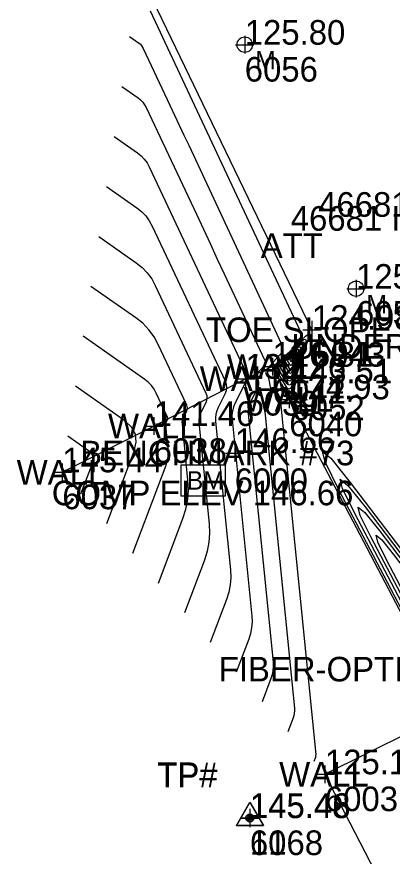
# Model space of a CAD drawing. Extents: x 13482745 to 13483091, y 311698 to 312158.
# Drawn here: x 13482867.1 to 13482915.9, y 311863.1 to 311972.3 of the extents above; entities that cross this region are included whole.
import ezdxf

# ---------------------------------------------------------------- set-up
doc = ezdxf.new("R2010")
doc.units = 0
for name, color, linetype in [('V-BLDG-OTLN', 7, 'Continuous'), ('V-PROP-IDEN', 7, 'Continuous'), ('V-PROP-MONM', 7, 'Continuous'), ('V-SITE-FEAT', 7, 'Continuous'), ('V-SITE-IDEN', 7, 'Continuous'), ('V-SITE-SPOT', 7, 'Continuous'), ('V-SURV-DATA', 7, 'Continuous'), ('V-SURV-IDEN', 7, 'Continuous'), ('V-SURV-PNTS', 7, 'Continuous'), ('V-SURV-SPOT', 7, 'Continuous'), ('V-TOPO-DRAN-SPOT', 7, 'Continuous'), ('V-TOPO-DRAN-TOE', 7, 'Continuous'), ('V-TOPO-LINE-IDEN', 7, 'Continuous'), ('V-TOPO-MAJR', 7, 'Continuous'), ('V-TOPO-MINR', 7, 'Continuous')]:
    doc.layers.add(name, color=color, linetype=linetype)

msp = doc.modelspace()

# ---------------------------------------------------------------- linework, layer by layer
at = {"layer": 'V-BLDG-OTLN'}
for points in [[(13482873.01, 311913.06), (13482884.9, 311919.08), (13482896.84, 311925.24), (13482900.36, 311926.81)], [(13482938.74, 311812.01), (13482914.39, 311859.78), (13482907.17, 311873.79), (13482923.79, 311882.04), (13482902.53, 311922.55), (13482900.37, 311926.81)]]:
    msp.add_lwpolyline(points, dxfattribs=at)
at = {"layer": 'V-SITE-FEAT'}
for centre in [(13482896.74, 311968.68), (13482911.22, 311936.94)]:
    msp.add_circle(centre, 1, dxfattribs=at)
at = {"layer": 'V-SITE-SPOT'}
for p, q in [((13482896.74, 311969.84), (13482896.74, 311967.52)), ((13482895.54, 311968.68), (13482897.94, 311968.68)), ((13482911.22, 311938.1), (13482911.22, 311935.78)), ((13482910.02, 311936.94), (13482912.42, 311936.94)), ((13482900.36, 311927.97), (13482900.36, 311925.65)), ((13482900.37, 311927.97), (13482900.37, 311925.65)), ((13482896.84, 311926.4), (13482896.84, 311924.08)), ((13482899.16, 311926.81), (13482901.56, 311926.81)), ((13482899.17, 311926.81), (13482901.57, 311926.81)), ((13482895.64, 311925.24), (13482898.04, 311925.24)), ((13482902.83, 311924.2), (13482902.83, 311921.88)), ((13482901.63, 311923.04), (13482904.03, 311923.04)), ((13482902.53, 311923.71), (13482902.53, 311921.39)), ((13482901.33, 311922.55), (13482903.73, 311922.55)), ((13482884.9, 311920.24), (13482884.9, 311917.92)), ((13482883.7, 311919.08), (13482886.1, 311919.08)), ((13482873.01, 311914.22), (13482873.01, 311911.9)), ((13482871.81, 311913.06), (13482874.21, 311913.06)), ((13482907.17, 311874.95), (13482907.17, 311872.63)), ((13482905.97, 311873.79), (13482908.37, 311873.79))]:
    msp.add_line(p, q, dxfattribs=at)
at = {"layer": 'V-SURV-DATA'}
for p, q in [((13482895.44, 311916.73), (13482895.44, 311914.41)), ((13482894.24, 311915.57), (13482896.64, 311915.57)), ((13482894.24, 311914.01), (13482888.41, 311914.01)), ((13482888.41, 311914.01), (13482888.41, 311910.01)), ((13482894.24, 311910.01), (13482894.24, 311914.01)), ((13482888.41, 311910.01), (13482894.24, 311910.01))]:
    msp.add_line(p, q, dxfattribs=at)
for points in [[(13482897.41, 311870.15), (13482899.17, 311867.11), (13482895.65, 311867.11)], [(13482897.41, 311870.15), (13482899.17, 311867.11), (13482895.65, 311867.11)], [(13482897.41, 311870.15), (13482899.17, 311867.11), (13482895.65, 311867.11)], [(13482897.41, 311870.1), (13482899.17, 311867.06), (13482895.65, 311867.06)]]:
    msp.add_lwpolyline(points, close=True, dxfattribs=at)
for centre, radius in [((13482897.41, 311868.13), 0.508), ((13482897.41, 311868.13), 0.508), ((13482897.41, 311868.13), 0.508), ((13482897.41, 311868.08), 0.508), ((13482897.41, 311868.08), 0.305), ((13482897.41, 311868.13), 0.305), ((13482897.41, 311868.13), 0.305), ((13482897.41, 311868.13), 0.305), ((13482897.41, 311868.13), 0.102), ((13482897.41, 311868.13), 0.102), ((13482897.41, 311868.13), 0.102), ((13482897.41, 311868.08), 0.102)]:
    msp.add_circle(centre, radius, dxfattribs=at)
at = {"layer": 'V-SURV-SPOT'}
for p, q in [((13482895.44, 311916.73), (13482895.44, 311914.41)), ((13482894.24, 311915.57), (13482896.64, 311915.57)), ((13482897.41, 311869.29), (13482897.41, 311866.97)), ((13482897.41, 311869.29), (13482897.41, 311866.97)), ((13482897.41, 311869.29), (13482897.41, 311866.97)), ((13482897.41, 311869.24), (13482897.41, 311866.92)), ((13482896.21, 311868.13), (13482898.61, 311868.13)), ((13482896.21, 311868.13), (13482898.61, 311868.13)), ((13482896.21, 311868.13), (13482898.61, 311868.13)), ((13482896.21, 311868.08), (13482898.61, 311868.08))]:
    msp.add_line(p, q, dxfattribs=at)
at = {"layer": 'V-TOPO-DRAN-SPOT'}
for p, q in [((13482905.49, 311932.76), (13482905.49, 311930.44)), ((13482904.29, 311931.6), (13482906.69, 311931.6))]:
    msp.add_line(p, q, dxfattribs=at)
at = {"layer": 'V-TOPO-DRAN-TOE'}
msp.add_lwpolyline([(13482905.49, 311931.6), (13482883.03, 311978.13)], dxfattribs=at)
at = {"layer": 'V-TOPO-MAJR'}
for points in [[(13482880.74, 311963.25), (13482882.86, 311961.77), (13482883.19, 311961.5), (13482883.48, 311961.2), (13482883.72, 311960.87), (13482883.93, 311960.49), (13482890.45, 311946.62), (13482891.36, 311944.68), (13482892.27, 311942.74), (13482893.17, 311940.8), (13482894.08, 311938.86), (13482899.34, 311927.62), (13482899.4, 311927.42), (13482899.4, 311927.23), (13482899.34, 311927.05), (13482899.22, 311926.88), (13482898.3, 311925.89), (13482898.3, 311925.89), (13482898.3, 311925.89), (13482898.52, 311924.78), (13482898.54, 311924.59), (13482898.54, 311924.41), (13482898.5, 311924.24), (13482898.43, 311924.07), (13482897.49, 311922.21), (13482897.33, 311921.84), (13482897.23, 311921.46), (13482897.19, 311921.07), (13482897.2, 311920.67), (13482900.43, 311888.36), (13482900.45, 311887.82), (13482900.41, 311887.29), (13482900.31, 311886.77), (13482900.15, 311886.25), (13482898.99, 311883.19)], [(13482882.17, 311902.53), (13482886.5, 311914.01), (13482886.66, 311914.53), (13482886.76, 311915.05), (13482886.8, 311915.58), (13482886.78, 311916.12), (13482886.47, 311919.2), (13482886.47, 311919.29), (13482886.48, 311919.38), (13482886.5, 311919.47), (13482886.54, 311919.55), (13482886.71, 311919.89), (13482886.74, 311919.97), (13482886.75, 311920.06), (13482886.74, 311920.14), (13482886.71, 311920.23), (13482885.24, 311923.35), (13482884.96, 311923.87), (13482884.61, 311924.34), (13482884.2, 311924.77), (13482883.74, 311925.14), (13482875.74, 311930.75)]]:
    msp.add_lwpolyline(points, dxfattribs=at)
for points in [[(13482902.74, 311924.5), (13482902.57, 311924.39), (13482902.38, 311924.47), (13482902.17, 311924.74), (13482900.84, 311927), (13482900.84, 311927.01), (13482900.84, 311927.01), (13482903.79, 311929.69), (13482904.19, 311930), (13482904.42, 311930.04), (13482904.48, 311929.82), (13482904.36, 311929.32), (13482902.89, 311924.82)], [(13482902.81, 311926.97), (13482902.77, 311926.94), (13482902.72, 311926.96), (13482902.66, 311927.03), (13482902.32, 311927.62), (13482902.32, 311927.62), (13482903.08, 311928.32), (13482903.19, 311928.4), (13482903.25, 311928.41), (13482903.26, 311928.35), (13482903.23, 311928.22), (13482902.85, 311927.06)], [(13482929.41, 311885.45), (13482929.47, 311885.05), (13482929.35, 311884.67), (13482929.07, 311884.3), (13482927.22, 311882.5), (13482927.02, 311882.34), (13482926.8, 311882.25), (13482926.57, 311882.21), (13482926.32, 311882.24), (13482925.27, 311882.49), (13482925.03, 311882.57), (13482924.82, 311882.7), (13482924.64, 311882.87), (13482924.5, 311883.08), (13482913.15, 311904.65), (13482911.78, 311907.46), (13482911.51, 311908.51), (13482912.36, 311907.83), (13482914.31, 311905.39), (13482929.18, 311885.85)]]:
    msp.add_lwpolyline(points, close=True, dxfattribs=at)
at = {"layer": 'V-TOPO-MINR'}
for points in [[(13482884.46, 311973.09), (13482904.02, 311931.26), (13482904.11, 311930.99), (13482904.11, 311930.74), (13482904.03, 311930.49), (13482903.87, 311930.26), (13482903.04, 311929.37), (13482902.89, 311929.21), (13482902.84, 311929.14), (13482902.91, 311929.19), (13482903.08, 311929.34), (13482904.67, 311930.78), (13482904.95, 311930.99), (13482905.1, 311931.02), (13482905.14, 311930.87), (13482905.06, 311930.52), (13482902.74, 311923.44), (13482902.64, 311923.21), (13482902.52, 311923.13), (13482902.39, 311923.19), (13482902.24, 311923.38), (13482901.56, 311924.53), (13482901.45, 311924.69), (13482901.39, 311924.73), (13482901.37, 311924.66), (13482901.4, 311924.46), (13482901.67, 311923.11), (13482901.68, 311923.02), (13482901.67, 311922.94), (13482901.66, 311922.86), (13482901.62, 311922.78), (13482901.47, 311922.48), (13482901.43, 311922.4), (13482901.41, 311922.32), (13482901.4, 311922.23), (13482901.41, 311922.15), (13482905.98, 311876.36), (13482905.98, 311876.27), (13482905.97, 311876.17), (13482905.96, 311876.08), (13482905.93, 311875.99), (13482905.72, 311875.45)], [(13482881.74, 311969.75), (13482882.93, 311968.92), (13482883.12, 311968.77), (13482883.28, 311968.6), (13482883.42, 311968.41), (13482883.53, 311968.2), (13482887, 311960.82), (13482887.62, 311959.51), (13482888.23, 311958.21), (13482888.84, 311956.9), (13482889.45, 311955.6), (13482901.54, 311929.73), (13482901.66, 311929.36), (13482901.67, 311929), (13482901.56, 311928.66), (13482901.33, 311928.34), (13482899.6, 311926.47), (13482899.6, 311926.47), (13482899.6, 311926.46), (13482899.6, 311926.46), (13482900.05, 311924.16), (13482900.08, 311923.92), (13482900.07, 311923.68), (13482900.02, 311923.45), (13482899.93, 311923.23), (13482899.48, 311922.34), (13482899.38, 311922.12), (13482899.32, 311921.89), (13482899.3, 311921.65), (13482899.31, 311921.41), (13482903.2, 311882.36), (13482903.22, 311882.05), (13482903.19, 311881.73), (13482903.13, 311881.42), (13482903.04, 311881.12), (13482902.36, 311879.32)], [(13482879.74, 311956.75), (13482882.78, 311954.62), (13482883.26, 311954.24), (13482883.67, 311953.8), (13482884.03, 311953.32), (13482884.32, 311952.79), (13482896.09, 311927.73), (13482896.2, 311927.5), (13482896.31, 311927.28), (13482896.41, 311927.05), (13482896.52, 311926.83), (13482897.13, 311925.51), (13482897.14, 311925.49), (13482897.14, 311925.47), (13482897.13, 311925.45), (13482897.12, 311925.43), (13482897.01, 311925.31), (13482897.01, 311925.31), (13482897.04, 311925.18), (13482897.04, 311925.16), (13482897.04, 311925.14), (13482897.03, 311925.12), (13482897.02, 311925.1), (13482895.5, 311922.08), (13482895.28, 311921.57), (13482895.15, 311921.03), (13482895.08, 311920.49), (13482895.1, 311919.93), (13482897.65, 311894.36), (13482897.69, 311893.6), (13482897.63, 311892.85), (13482897.49, 311892.11), (13482897.26, 311891.38), (13482895.63, 311887.06)], [(13482878.74, 311950.25), (13482882.71, 311947.47), (13482883.33, 311946.97), (13482883.87, 311946.41), (13482884.33, 311945.78), (13482884.72, 311945.08), (13482894.18, 311924.94), (13482894.33, 311924.51), (13482894.37, 311924.08), (13482894.32, 311923.65), (13482894.15, 311923.22), (13482893.29, 311921.5), (13482893.1, 311921.07), (13482892.99, 311920.62), (13482892.94, 311920.16), (13482892.95, 311919.69), (13482894.88, 311900.36), (13482894.92, 311899.38), (13482894.85, 311898.41), (13482894.67, 311897.46), (13482894.37, 311896.52), (13482892.26, 311890.93)], [(13482877.74, 311943.75), (13482882.63, 311940.32), (13482883.4, 311939.71), (13482884.07, 311939.01), (13482884.64, 311938.23), (13482885.11, 311937.37), (13482891.69, 311923.37), (13482891.8, 311923.05), (13482891.83, 311922.74), (13482891.79, 311922.42), (13482891.67, 311922.11), (13482891.04, 311920.85), (13482890.9, 311920.53), (13482890.82, 311920.21), (13482890.78, 311919.87), (13482890.79, 311919.52), (13482892.1, 311906.36), (13482892.16, 311905.16), (13482892.07, 311903.97), (13482891.85, 311902.8), (13482891.49, 311901.65), (13482888.9, 311894.79)], [(13482885.53, 311898.66), (13482888.7, 311907.06), (13482889.09, 311908.28), (13482889.32, 311909.52), (13482889.42, 311910.78), (13482889.36, 311912.06), (13482888.63, 311919.36), (13482888.62, 311919.58), (13482888.65, 311919.79), (13482888.7, 311920), (13482888.79, 311920.2), (13482889.19, 311921), (13482889.26, 311921.2), (13482889.29, 311921.4), (13482889.27, 311921.6), (13482889.2, 311921.8), (13482885.5, 311929.67), (13482884.94, 311930.69), (13482884.26, 311931.61), (13482883.47, 311932.44), (13482882.56, 311933.17), (13482876.74, 311937.25)], [(13482878.81, 311906.4), (13482882.36, 311915.82), (13482882.63, 311916.98), (13482882.51, 311918.02), (13482882.02, 311918.95), (13482881.14, 311919.76), (13482874.74, 311924.25)], [(13482875.44, 311910.27), (13482876.93, 311914.22), (13482877.04, 311914.7), (13482876.99, 311915.14), (13482876.79, 311915.53), (13482876.42, 311915.87), (13482873.73, 311917.75)], [(13482923.92, 311882.38), (13482908.98, 311910.78), (13482907.19, 311914.42), (13482906.84, 311915.79), (13482907.94, 311914.9), (13482910.48, 311911.74), (13482930.23, 311885.79)], [(13482924.12, 311882.91), (13482911.06, 311907.72), (13482909.48, 311910.94), (13482909.18, 311912.15), (13482910.15, 311911.36), (13482912.4, 311908.57), (13482929.51, 311886.07)]]:
    msp.add_lwpolyline(points, dxfattribs=at)
for points in [[(13482902.73, 311924.01), (13482902.53, 311923.87), (13482902.32, 311923.97), (13482902.07, 311924.29), (13482900.55, 311926.88), (13482900.54, 311926.89), (13482900.54, 311926.89), (13482900.54, 311926.89), (13482903.93, 311929.96), (13482904.39, 311930.32), (13482904.66, 311930.37), (13482904.72, 311930.11), (13482904.58, 311929.54), (13482902.89, 311924.37)], [(13482902.75, 311925), (13482902.61, 311924.9), (13482902.45, 311924.97), (13482902.27, 311925.2), (13482901.14, 311927.13), (13482901.13, 311927.13), (13482901.13, 311927.13), (13482903.65, 311929.42), (13482903.99, 311929.68), (13482904.19, 311929.72), (13482904.23, 311929.52), (13482904.13, 311929.1), (13482902.88, 311925.27)], [(13482902.77, 311925.49), (13482902.65, 311925.41), (13482902.52, 311925.46), (13482902.37, 311925.66), (13482901.43, 311927.25), (13482901.43, 311927.25), (13482901.43, 311927.26), (13482903.51, 311929.14), (13482903.79, 311929.36), (13482903.95, 311929.39), (13482903.99, 311929.23), (13482903.91, 311928.88), (13482902.87, 311925.71)], [(13482902.78, 311925.99), (13482902.69, 311925.92), (13482902.58, 311925.96), (13482902.47, 311926.12), (13482901.73, 311927.37), (13482901.72, 311927.38), (13482901.72, 311927.38), (13482903.36, 311928.87), (13482903.59, 311929.04), (13482903.72, 311929.06), (13482903.75, 311928.94), (13482903.68, 311928.66), (13482902.86, 311926.16)], [(13482902.8, 311926.48), (13482902.73, 311926.43), (13482902.65, 311926.46), (13482902.56, 311926.58), (13482902.02, 311927.5), (13482902.02, 311927.5), (13482902.02, 311927.5), (13482903.22, 311928.59), (13482903.39, 311928.72), (13482903.48, 311928.74), (13482903.5, 311928.65), (13482903.46, 311928.44), (13482902.86, 311926.61)], [(13482902.82, 311927.47), (13482902.8, 311927.45), (13482902.78, 311927.46), (13482902.76, 311927.49), (13482902.61, 311927.75), (13482902.61, 311927.75), (13482902.94, 311928.05), (13482902.99, 311928.08), (13482903.01, 311928.09), (13482903.02, 311928.06), (13482903, 311928), (13482902.84, 311927.5)], [(13482929.08, 311885.24), (13482929.13, 311884.9), (13482929.03, 311884.58), (13482928.79, 311884.26), (13482927.22, 311882.73), (13482927.05, 311882.59), (13482926.86, 311882.51), (13482926.66, 311882.49), (13482926.45, 311882.51), (13482925.56, 311882.72), (13482925.35, 311882.79), (13482925.17, 311882.9), (13482925.02, 311883.04), (13482924.9, 311883.22), (13482915.24, 311901.59), (13482914.07, 311903.97), (13482913.84, 311904.87), (13482914.56, 311904.29), (13482916.23, 311902.22), (13482928.89, 311885.58)]]:
    msp.add_lwpolyline(points, close=True, dxfattribs=at)

# ---------------------------------------------------------------- texts
at = {"layer": 'V-PROP-IDEN'}
for p in [(13482885.37, 311872.13), (13482885.37, 311872.13), (13482885.37, 311872.13), (13482885.37, 311872.08)]:
    msp.add_text('TP#', height=3.2, dxfattribs=at).set_placement(p)
at = {"layer": 'V-PROP-MONM'}
for p in [(13482906.29, 311946.3), (13482902.73, 311944.48)]:
    msp.add_text('46681 IR', height=3.2, dxfattribs=at).set_placement(p)
at = {"layer": 'V-SITE-FEAT'}
for p in [(13482898.1, 311965.48), (13482912.58, 311933.74)]:
    msp.add_text('M', height=2.4, rotation=360, dxfattribs=at).set_placement(p)
at = {"layer": 'V-SITE-IDEN'}
for s, p in [('ATT', (13482898.83, 311940.94)), ('UNDERCLEAR', (13482902.83, 311927.84)), ('FIBER-OPTIC', (13482893.36, 311885.86))]:
    msp.add_text(s, height=3.2, dxfattribs=at).set_placement(p)
at = {"layer": 'V-SITE-SPOT'}
for s, p in [('125.80', (13482896.74, 311968.68)), ('125.30', (13482911.22, 311936.94)), ('126.81', (13482900.36, 311926.81)), ('126.81', (13482900.37, 311926.81)), ('132.26', (13482896.84, 311925.24)), ('143.51', (13482902.83, 311924.64)), ('124.93', (13482902.53, 311922.55)), ('141.46', (13482884.9, 311919.08)), ('145.44', (13482873.01, 311913.06)), ('125.14', (13482907.17, 311873.79))]:
    msp.add_text(s, height=3.2, dxfattribs=at).set_placement(p)
at = {"layer": 'V-SURV-DATA'}
msp.add_text('BM', height=2.4, rotation=360, dxfattribs=at).set_placement((13482889.21, 311910.81))
at = {"layer": 'V-SURV-IDEN'}
for s, p in [('BENCHMARK #73', (13482875.33, 311913.97)), ('COMP ELEV 146.66', (13482871.63, 311908.77))]:
    msp.add_text(s, height=3.2, dxfattribs=at).set_placement(p)
at = {"layer": 'V-SURV-PNTS'}
for s, p in [('6056', (13482896.74, 311963.88)), ('6055', (13482911.22, 311932.14)), ('6043', (13482905.49, 311926.8)), ('6042', (13482900.36, 311922.01)), ('6041', (13482900.37, 311922.01)), ('6039', (13482896.84, 311920.44)), ('6052', (13482902.83, 311919.84)), ('6040', (13482902.53, 311917.75)), ('6038', (13482884.9, 311914.28)), ('6000', (13482895.44, 311910.37)), ('6037', (13482873.01, 311908.26)), ('6003', (13482907.17, 311868.99)), ('6068', (13482897.41, 311863.28)), ('11', (13482897.41, 311863.33)), ('11', (13482897.41, 311863.33)), ('11', (13482897.41, 311863.33))]:
    msp.add_text(s, height=3.2, dxfattribs=at).set_placement(p)
at = {"layer": 'V-SURV-SPOT'}
for s, p in [('146.66', (13482895.44, 311915.57)), ('145.48', (13482897.41, 311868.08)), ('145.46', (13482897.41, 311868.13)), ('145.46', (13482897.41, 311868.13)), ('145.46', (13482897.41, 311868.13))]:
    msp.add_text(s, height=3.2, dxfattribs=at).set_placement(p)
at = {"layer": 'V-TOPO-DRAN-SPOT'}
msp.add_text('124.98', height=3.2, dxfattribs=at).set_placement((13482905.49, 311931.6))
at = {"layer": 'V-TOPO-LINE-IDEN'}
for s, p in [('TOE SLOPE', (13482891.7, 311930)), ('WALL', (13482894.42, 311925.21)), ('WALL', (13482894.42, 311925.21)), ('WALL', (13482890.89, 311923.64)), ('WALL', (13482896.59, 311920.95)), ('WALL', (13482878.95, 311917.48)), ('WALL', (13482867.07, 311911.46)), ('WALL', (13482901.22, 311872.19))]:
    msp.add_text(s, height=3.2, dxfattribs=at).set_placement(p)

doc.saveas('drawing.dxf')
